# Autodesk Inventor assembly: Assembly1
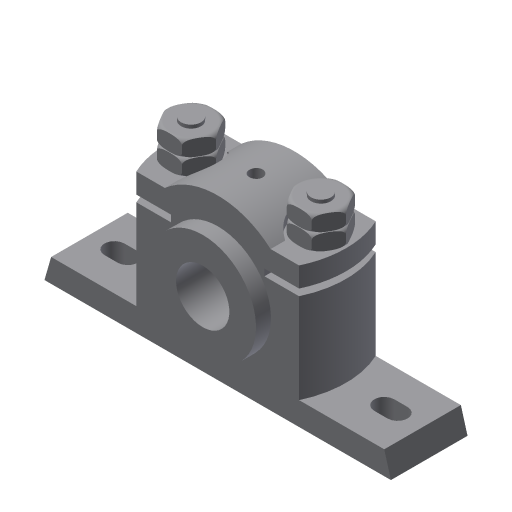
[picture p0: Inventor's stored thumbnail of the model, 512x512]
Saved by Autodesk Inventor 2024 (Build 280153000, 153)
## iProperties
Created: 2016-03
Part Number: Assembly1
Document SubType Name: Assembly
Designer: Sandeep
Author: Sandeep
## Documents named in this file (7)
- D:\PROJECTS\Project 2023\RESOURCES INVENTOR 2024\RESOURCES INVENTOR 2024\Inventor_2024_tut\Inventor_2024_tut\c13_Inv_2024_tut\c13_Inv_tut_2024\c13-tut01-inv\Plummer block\Assembly1.iam
- D:\PROJECTS\Project 2023\RESOURCES INVENTOR 2024\RESOURCES INVENTOR 2024\Inventor_2024_tut\Inventor_2024_tut\c13_Inv_2024_tut\c13_Inv_tut_2024\c13-tut01-inv\Plummer block\Casting.ipt
- D:\PROJECTS\Project 2023\RESOURCES INVENTOR 2024\RESOURCES INVENTOR 2024\Inventor_2024_tut\Inventor_2024_tut\c13_Inv_2024_tut\c13_Inv_tut_2024\c13-tut01-inv\Plummer block\Brasses.ipt
- D:\PROJECTS\Project 2023\RESOURCES INVENTOR 2024\RESOURCES INVENTOR 2024\Inventor_2024_tut\Inventor_2024_tut\c13_Inv_2024_tut\c13_Inv_tut_2024\c13-tut01-inv\Plummer block\Cap.ipt
- D:\PROJECTS\Project 2023\RESOURCES INVENTOR 2024\RESOURCES INVENTOR 2024\Inventor_2024_tut\Inventor_2024_tut\c13_Inv_2024_tut\c13_Inv_tut_2024\c13-tut01-inv\Plummer block\Bolt.ipt
- D:\PROJECTS\Project 2023\RESOURCES INVENTOR 2024\RESOURCES INVENTOR 2024\Inventor_2024_tut\Inventor_2024_tut\c13_Inv_2024_tut\c13_Inv_tut_2024\c13-tut01-inv\Plummer block\Nut.ipt
- D:\PROJECTS\Project 2023\RESOURCES INVENTOR 2024\RESOURCES INVENTOR 2024\Inventor_2024_tut\Inventor_2024_tut\c13_Inv_2024_tut\c13_Inv_tut_2024\c13-tut01-inv\Plummer block\Lock Nut.ipt
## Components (9 placed, 6 different names)
1. Casting:1 — Mate:1, Mate:2, Insert:1, Insert:2, Angle:1, Angle:2
2. Brasses:1 — Mate:1, Mate:2, Mate:3, Mate:4
3. Cap:1 — Mate:3, Mate:4, Insert:3, Insert:5
4. Bolt:1 — Insert:1, Angle:1
5. Bolt:2 — Insert:2, Angle:2
6. Nut:1 — Insert:3, Insert:4
7. Nut:2 — Insert:5, Insert:6
8. Lock Nut:1 — Insert:4
9. Lock Nut:2 — Insert:6
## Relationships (12: Insert 6, Mate 4, Angle 2)
- Mate:1: Casting:1 ↔ Brasses:1
- Mate:2: Casting:1 ↔ Brasses:1
- Mate:3: Brasses:1 ↔ Cap:1
- Mate:4: Brasses:1 ↔ Cap:1
- Insert:1: Casting:1 ↔ Bolt:1
- Insert:2: Casting:1 ↔ Bolt:2
- Angle:1: Casting:1 ↔ Bolt:1
- Angle:2: Casting:1 ↔ Bolt:2
- Insert:3: Cap:1 ↔ Nut:1
- Insert:4: Nut:1 ↔ Lock Nut:1
- Insert:5: Cap:1 ↔ Nut:2
- Insert:6: Nut:2 ↔ Lock Nut:2
